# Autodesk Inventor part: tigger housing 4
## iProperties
Created: 2006-04
Part Number: tigger housing 4
Checked By: Проверил
Material: Обычный
Description: Наименование
Document SubType Name: Modeling
Mfg Approved By: Утвердил
Designer: Калинин
Engineer: Технолог
Manufacturer: Standard
Standards Organization: Custom
Author: Калинин
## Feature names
1. Выдавливание4 [Extrusion]
2. Выдавливание5 [Extrusion]
3. Выдавливание6 [Extrusion]
4. Сопряжение1 [Fillet]
